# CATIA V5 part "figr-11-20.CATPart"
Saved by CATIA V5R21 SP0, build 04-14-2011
Part number: Part5
Bounding box of the stored display mesh (mm): x -70 to 70, y -150 to 0, z -1.939 to 20.996
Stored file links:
  D:\CATIA V5R21 E-RESOURCES\CATIA-V5R21\catia-v5r21-prt\c11-catia-v5r21-prt\c11-catia-v5r21-figr-11-20.CATPart
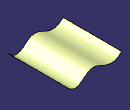
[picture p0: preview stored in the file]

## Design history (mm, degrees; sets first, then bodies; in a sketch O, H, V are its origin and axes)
Body1 (main body)
  Sketch1 on zx-plane, origin (0, 0, 0), H (-1, 0, 0), V (0, 0, 1)
    spline S1 through (-70, 10) (-40, 0) (-10, 20) (30, 10) (70, 20)
  Extrude1: Lim1 150, Lim2 0, Element1 Sketch1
